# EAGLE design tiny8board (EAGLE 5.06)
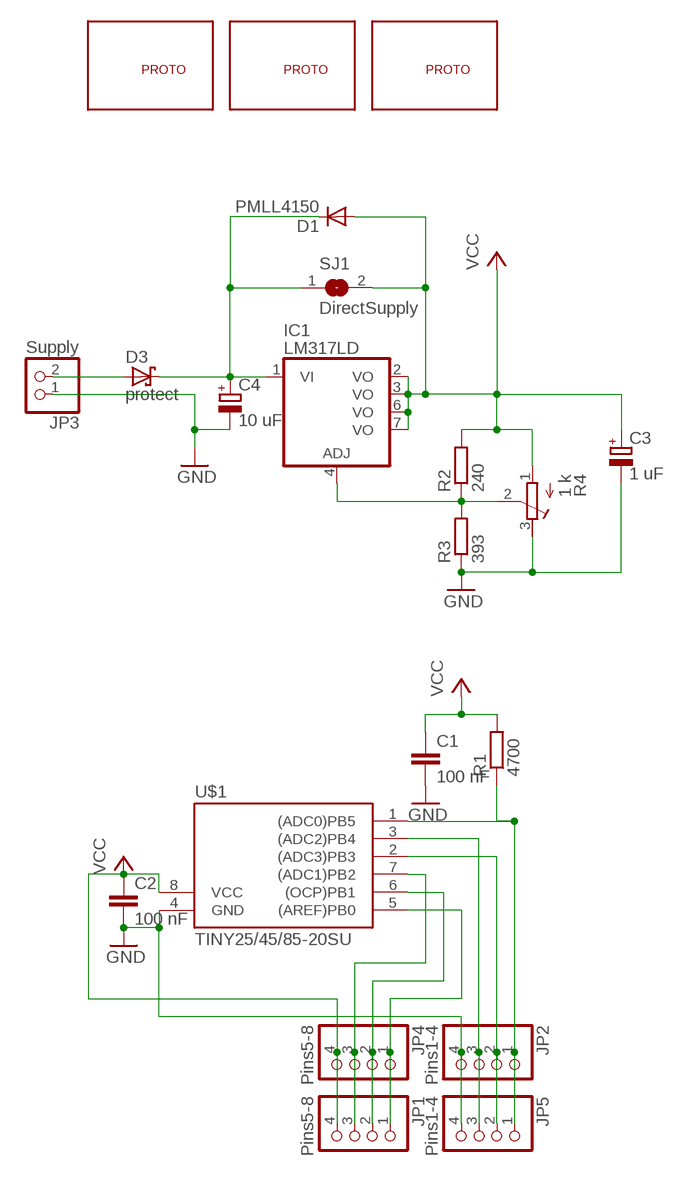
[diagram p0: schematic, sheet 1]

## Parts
C1  100 nF  C-EUC0805  [C0805]
C2  100 nF  C-EUC0805  [C0805]
C3  1 uF  CPOL-EU153CLV-0405  [153CLV-0405]
C4  10 uF  CPOL-EU153CLV-0405  [153CLV-0405]
D1  PMLL4150  [SOD80C]
D3  protect  SCHOTTKY-DIODESMD  [SMB]
IC1  LM317LD  [SO08]
JP1  Pins5-8  PINHD-1X4  [1X04]
JP2  Pins1-4  PINHD-1X4  [1X04]
JP3  Supply  PINHD-1X2  [1X02]
JP4  Pins5-8  PINHD-1X4  [1X04]
JP5  Pins1-4  PINHD-1X4  [1X04]
R1  4700  R-EU_R0805  [R0805]
R2  240  R-EU_R0805  [R0805]
R3  393  R-EU_R0805  [R0805]
R4  1 k  R-TRIMM3165W  [RTRIM3165W]
SJ1  DirectSupply  SJ  [SJ]
U$1  TINY25/45/85-20SU  [SOIC8]
U$2  PROTO-AREA  [PROTO-AREA]
U$3  PROTO-AREA  [PROTO-AREA]  (not placed on a sheet)
U$4  PROTO-AREA  [PROTO-AREA]
U$5  PROTO-AREA  [PROTO-AREA]

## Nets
GND: C1.2 C2.2 C3.- C4.- JP2.4 JP3.1 JP5.4 R3.1 R4.3(A) U$1.4(GND)
N$1: JP2.1 JP5.1 R1.1 U$1.1((ADC0)PB5)
N$2: C4.+ D1.C D3.C IC1.1(VI) SJ1.1
N$3: JP1.1 JP4.1 U$1.5((AREF)PB0)
N$4: JP1.2 JP4.2 U$1.6((OCP)PB1)
N$5: JP1.3 JP4.3 U$1.7((ADC1)PB2)
N$6: JP2.2 JP5.2 U$1.2((ADC3)PB3)
N$7: IC1.4(ADJ) R2.1 R3.2 R4.2(S)
N$8: JP2.3 JP5.3 U$1.3((ADC2)PB4)
N$9: D3.A JP3.2
VCC: C1.1 C2.1 C3.+ D1.A IC1.2(VO) IC1.3(VO) IC1.6(VO) IC1.7(VO) JP1.4 JP4.4 R1.2 R2.2 R4.1(E) SJ1.2 U$1.8(VCC)

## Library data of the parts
C1 C2 = rcl:C-EU: CAPACITOR, European symbol
C3 C4 = rcl:CPOL-EU: POLARIZED CAPACITOR, European symbol
D1 = diode:PMLL4150: DIODE
D3 = diode:SCHOTTKY-DIODE: Schottky Diode
IC1 = linear:LM317LD: LOW CURRENT 1.2 TO 37V ADJUSTABLE VOLTAGE REGULATOR Source: http://pdf.alldatasheet.com
JP1 JP2 JP4 JP5 = pinhead:PINHD-1X4: PIN HEADER
JP3 = pinhead:PINHD-1X2: PIN HEADER
R1-R3 = rcl:R-EU_: RESISTOR, European symbol
R4 = rcl:R-TRIMM: Trimm resistor
SJ1 = jumper:SJ: SMD solder JUMPER
U$1 = avr-6:TINY25/45/85
U$2-U$5 = proto:PROTO-AREA

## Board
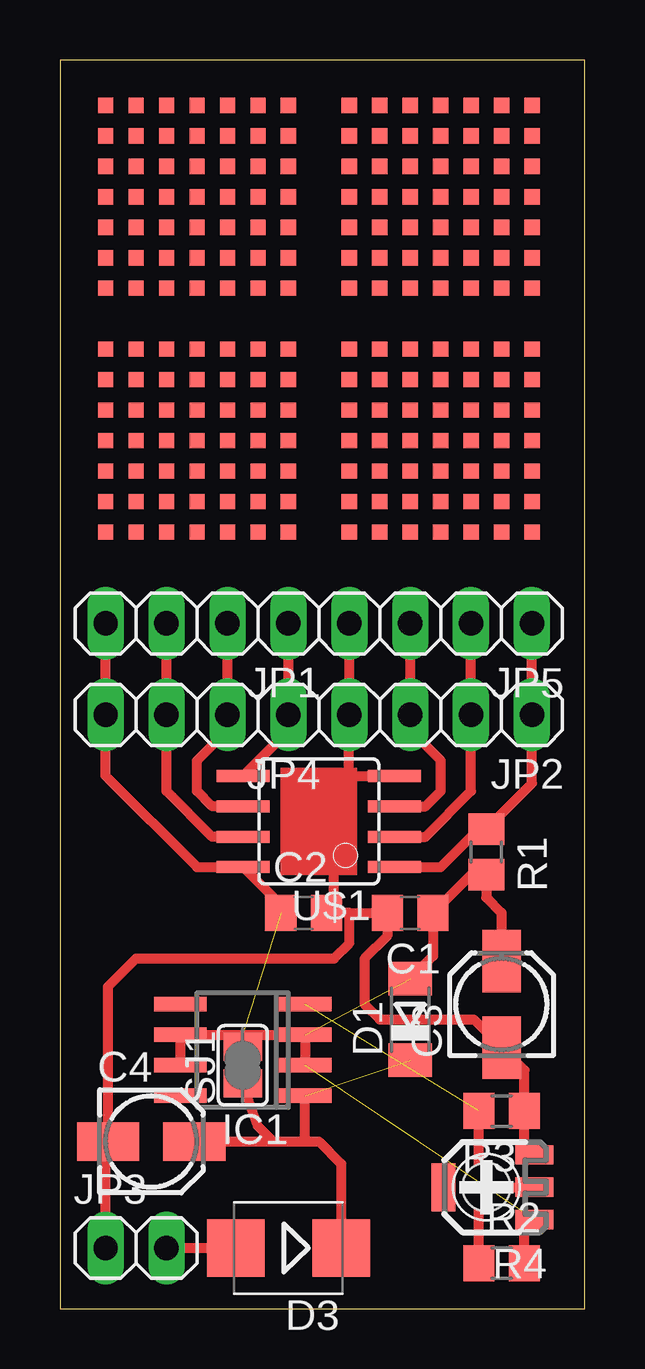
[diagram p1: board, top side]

Size 21.89 x 52.06 mm. Coordinates in mm from the lower left corner, seen from the top.
Outline: 0,0 21.89,0 21.89,52.06 0,52.06 0,0
Copper layers (1*16): Top 0.035mm / dielectric 1.5mm / Bottom 0.035mm
Design rules "default": minimum track width 10mil, minimum drill 24mil, track to track 8mil, track to pad 8mil, pad to pad 8mil, via to via 8mil, smd to smd 8mil, copper to edge 40mil, drill to drill 8mil, minimum pad ring 10mil, minimum via ring 8mil, stop-mask expansion 4mil, vias tented up to drill 0mil, thermal gap 10mil

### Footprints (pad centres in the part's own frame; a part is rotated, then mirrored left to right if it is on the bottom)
C0805 = smd 1.3 x 1.5: 1 -0.95,0; 2 0.95,0
153CLV-0405 = smd 2.6 x 1.6: + 1.8,0; - -1.8,0
SOD80C = smd 1.4 x 1.8: A 1.7,0; C -1.7,0
SMB = smd 2.4 x 2.4: A 2.2,0; C -2.2,0
SO08 = smd 0.6 x 2.2: 1 -1.905,-2.6; 2 -0.635,-2.6; 3 0.635,-2.6; 4 1.905,-2.6; 5 1.905,2.6; 6 0.635,2.6; 7 -0.635,2.6; 8 -1.905,2.6
1X04 = drill 1.016 long: 1 -3.81,0; 2 -1.27,0; 3 1.27,0; 4 3.81,0
1X02 = drill 1.016 long: 1 -1.27,0; 2 1.27,0
R0805 = smd 1.3 x 1.5: 1 -0.95,0; 2 0.95,0
RTRIM3165W = smd 0.8 x 1.6: 1 -1.35,-2; 2 0,-2; 3 1.35,-2 | smd 2 x 1: 4 0,1.8 | hole 2: 0,0
SJ = smd 1.168 x 1.6: 1 -0.762,0; 2 0.762,0
SOIC8 = smd 0.5 x 2.2: 1 -1.905,-3.154; 2 -0.645,-3.154; 3 0.625,-3.154; 4 1.895,-3.154; 5 1.905,3.154; 6 0.635,3.154; 7 -0.635,3.154; 8 -1.905,3.154
PROTO-AREA = smd 0.635 x 0.635: P$2 -3.81,3.81; P$3 -2.54,3.81; P$4 -2.54,2.54; P$5 -3.81,2.54; P$6 -1.27,3.81; P$7 -1.27,2.54; P$8 0,2.54; P$9 0,3.81; P$10 1.27,3.81; P$11 1.27,2.54; P$12 2.54,2.54; P$13 2.54,3.81; P$14 -3.81,1.27; P$15 -2.54,1.27; P$16 -1.27,1.27; P$17 0,1.27; P$18 1.27,1.27; P$19 2.54,1.27; P$20 2.54,0; P$21 1.27,0; P$22 0,0; P$23 -1.27,0; P$24 -2.54,0; P$25 -3.81,0; P$26 -3.81,-1.27; P$27 -2.54,-1.27; P$28 -1.27,-1.27; P$29 0,-1.27; P$30 1.27,-1.27; P$31 2.54,-1.27; P$32 2.54,-2.54; P$33 1.27,-2.54; P$34 0,-2.54; P$35 -1.27,-2.54; P$36 -2.54,-2.54; P$37 -3.81,-2.54; P$38 -3.81,-3.81; P$39 -2.54,-3.81; P$40 -1.27,-3.81; P$41 0,-3.81; P$42 1.27,-3.81; P$43 2.54,-3.81; P$44 3.81,-3.81; P$45 3.81,-2.54; P$46 3.81,-1.27; P$47 3.81,0; P$48 3.81,1.27; P$49 3.81,2.54; P$50 3.81,3.81

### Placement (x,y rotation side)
C1  14.61,16.51 180 top
C2  10.16,16.51 0 top
C3  18.41,12.7 90 top
C4  3.81,6.99 0 top
D1  14.61,12.06 90 top
D3  9.53,2.54 180 top
IC1  7.62,10.79 90 top
JP1  5.71,28.57 180 top
JP2  15.88,24.77 180 top
JP3  3.17,2.54 0 top
JP4  5.71,24.77 180 top
JP5  15.88,28.57 180 top
R1  17.78,19.05 270 top
R2  18.41,1.91 0 top
R3  18.41,8.26 180 top
R4  17.78,5.08 90 top
SJ1  7.62,10.16 90 top
U$1  10.79,20.32 90 top
U$2  5.71,36.2 0 top
U$3  15.88,36.2 0 top
U$4  5.71,46.35 0 top
U$5  15.88,46.35 0 top

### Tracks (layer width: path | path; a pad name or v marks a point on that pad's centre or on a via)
GND
  Top 0.406: 12.05,22.21 U$1.4 | 12.05,22.21 11.43,21.59 11.43,16.83 C2.2 12.06,16.51 | 12.06,16.51 C1.2 13.65,15.56 12.7,14.61 12.7,12.7 13.34,12.06 17.25,12.06 C3.- 19.36,9.95 R3.1 19.36,6.84 R4.3 | 12.05,22.21 12.05,24.75 JP2.4 JP5.4 | JP3.1 1.91,6.88 C4.- 2.01,13.44 3.17,14.61 11.43,14.61 12.06,15.24 12.06,16.51
N$1
  Top 0.406: U$1.1 15.88,18.41 17.46,20 R1.1 19.68,21.91 JP2.1 JP5.1
N$2  (1 unrouted)
  Top 0.406: C4.+ 8.89,6.99 | 8.89,6.99 8.26,7.62 SJ1.1 | D3.C 11.72,6.05 10.79,6.99 10.16,6.99 | 8.89,6.99 10.16,6.99 | IC1.1 10.22,7.04 10.16,6.99
N$3
  Top 0.406: U$1.5 9.53,24.11 JP4.1 JP1.1
N$4
  Top 0.406: U$1.6 6.35,20.95 5.71,21.59 5.71,22.86 6.99,24.13 JP4.2 JP1.2
N$5
  Top 0.406: U$1.7 6.35,19.68 4.45,21.59 JP4.3 JP1.3
N$6
  Top 0.406: U$1.2 15.24,19.68 17.14,21.59 JP2.2 JP5.2
N$7  (1 unrouted)
  Top 0.406: R2.1 17.46,4.13 18.41,5.08 | 18.41,5.08 R4.2 | R3.2 17.46,6.03 18.41,5.08
N$8
  Top 0.406: U$1.3 15.24,20.95 15.88,21.59 15.88,22.86 14.61,24.13 JP2.3 JP5.3
N$9
  Top 0.406: JP3.2 D3.A
VCC  (3 unrouted)
  Top 0.406: C2.1 9.21,16.85 U$1.8 5.71,18.41 1.91,22.23 JP4.4 JP1.4 | IC1.7 IC1.6 7.62,11.43 | IC1.2 IC1.3 7.62,11.43 | 7.62,11.43 SJ1.2 | R2.2 19.36,3.31 R4.1 | C3.+ 18.41,16.51 17.78,17.14 R1.2 17.14,18.1 C1.1 15.55,14.71 D1.A
(copper drawn outside any net)
  shapes: Top area x1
